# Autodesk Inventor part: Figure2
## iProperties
Shininess: 77.0
Length Units: 11269
Angle Units: 11279
Time Units: 11290
Mass Units: 11283
Length Display Precision: 3
Angle Display Precision: 2
Created: 2001-12
Part Number: Figure2
Document SubType Name: Modeling
Designer: CADSoft
Density: 1 g/cm^3
Density: 0.0
Volumn: 0.0
Area: 0.0
PropertySet Name: Model Information
Control State: 0
Master: False
Checked Out: False
Author: CADSoft
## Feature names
1. Sweep6
